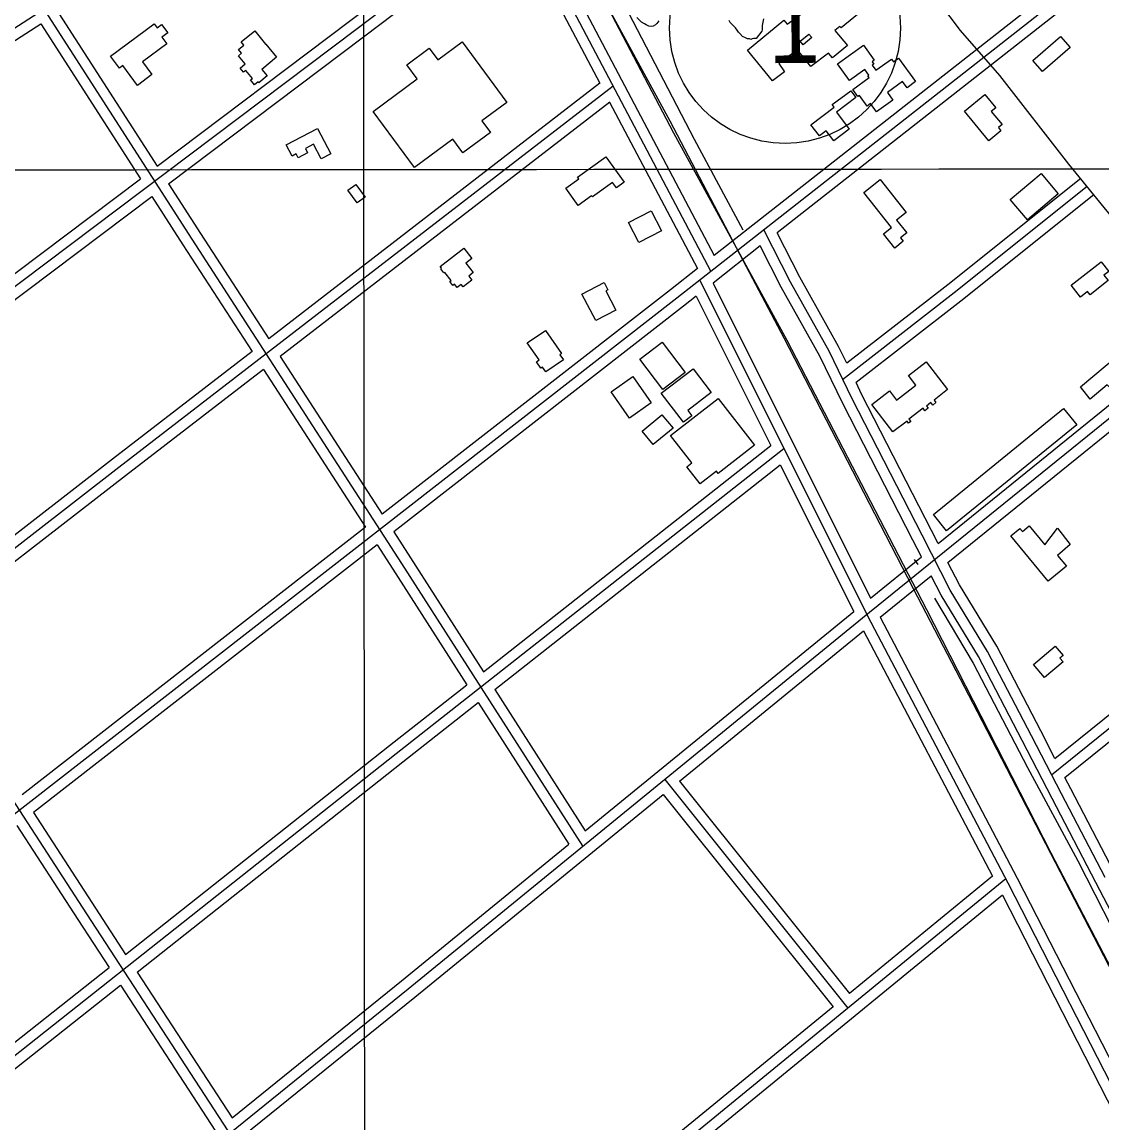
# Model space of a CAD drawing. Extents: x 3297772 to 3335630, y 634068 to 659439.
# Drawn here: x 3311908 to 3313452, y 647184 to 648757 of the extents above; entities that cross this region are included whole.
import ezdxf

# ---------------------------------------------------------------- set-up
doc = ezdxf.new("R2010")
doc.units = 0
for name, color, linetype in [('V-BLDG-OTLN', 7, 'Continuous'), ('V-GRID-MAJR', 7, 'Continuous'), ('V-RAIL-TRAK', 7, 'Continuous'), ('V-ROAD-CNTR', 7, 'Continuous'), ('V-ROAD-IDEN', 7, 'Continuous'), ('V-SITE-VEGE', 7, 'Continuous'), ('V-TOPO-SHOR', 7, 'Continuous')]:
    doc.layers.add(name, color=color, linetype=linetype)

msp = doc.modelspace()

# ---------------------------------------------------------------- linework, layer by layer
at = {"layer": 'V-BLDG-OTLN'}
for points in [[(3313109.589, 648773.9890000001), (3313078.918, 648748.635), (3313077.075, 648750.861), (3313069.884, 648744.902), (3313087.804, 648723.281), (3313066.599, 648705.703), (3313060.929, 648712.5430000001), (3313035.2630000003, 648693.395), (3313016.569, 648717.3250000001), (3312989.748, 648697.615), (3312997.883, 648685.653), (3312980.67, 648673.103), (3312944.932, 648716.899), (3312996.683, 648759.797), (3313001.578, 648753.89), (3313049.204, 648788.317), (3313047.8850000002, 648790.65), (3313079.5470000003, 648814.89)], [(3312034.455, 648708.253), (3312096.5870000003, 648754.341), (3312100.869, 648748.566), (3312107.47, 648753.46), (3312116.11, 648741.809), (3312107.7770000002, 648735.626), (3312115.045, 648725.829), (3312080.168, 648699.958), (3312093.578, 648681.881), (3312072.7970000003, 648666.4670000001), (3312051.838, 648694.7220000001), (3312047.099, 648691.205)], [(3312271.8850000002, 648706.702), (3312250.529, 648689.358), (3312258.1720000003, 648679.943), (3312246.1580000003, 648670.189), (3312245.2060000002, 648671.36), (3312240.1410000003, 648667.248), (3312234.399, 648674.319), (3312237.125, 648676.533), (3312227.88, 648687.9180000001), (3312224.5810000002, 648685.2390000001), (3312219.684, 648691.269), (3312226.903, 648697.132), (3312217.3140000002, 648708.941), (3312221.8200000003, 648712.599), (3312217.521, 648717.889), (3312225.035, 648723.99), (3312221.193, 648728.723), (3312240.514, 648744.412), (3312255.86, 648725.517), (3312256.554, 648725.581)], [(3313036.8170000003, 648734.731), (3313024.362, 648724.4500000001), (3313020.094, 648729.6240000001), (3313032.5470000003, 648739.903)], [(3312469.003, 648548.963), (3312409.81, 648629.028), (3312472.87, 648675.649), (3312457.946, 648695.834), (3312489.889, 648719.449), (3312502.134, 648702.885), (3312536.923, 648728.606), (3312600.907, 648642.059), (3312565.071, 648615.566), (3312577.345, 648598.963), (3312538.238, 648570.052), (3312523.849, 648589.512)], [(3313073.606, 648697.044), (3313110.613, 648723.783), (3313126.055, 648702.408), (3313123.0810000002, 648700.259), (3313125.531, 648696.87), (3313123.3370000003, 648695.285), (3313128.517, 648688.115), (3313150.731, 648704.165), (3313153.576, 648700.231), (3313161, 648705.594), (3313185.2770000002, 648671.991), (3313173.055, 648663.16), (3313166.659, 648672.013), (3313144.915, 648656.305), (3313152.882, 648645.279), (3313129.565, 648628.434), (3313120.88, 648640.456), (3313115.9790000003, 648636.915), (3313105.0100000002, 648652.0970000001), (3313102.661, 648650.4010000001), (3313095.276, 648660.62), (3313118.717, 648677.555), (3313117.031, 648679.89), (3313118.361, 648680.853), (3313112.522, 648688.936), (3313090.801, 648673.242)], [(3313352.898, 648702.004), (3313392.424, 648736.21), (3313405.969, 648720.557), (3313366.443, 648686.351)], [(3313068.5100000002, 648587.083), (3313057.551, 648601.609), (3313047.698, 648594.175), (3313035.56, 648610.2660000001), (3313068.86, 648635.389), (3313066.188, 648638.93), (3313092.519, 648658.796), (3313099.72, 648649.252), (3313071.93, 648628.285), (3313090.489, 648603.6630000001)], [(3313290.075, 648587.279), (3313255.241, 648629.485), (3313284.1380000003, 648653.336), (3313299.699, 648634.484), (3313293.401, 648629.2880000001), (3313308.919, 648610.4890000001), (3313303.498, 648606.015), (3313307.2290000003, 648601.437)], [(3312324.697, 648582.2000000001), (3312312.966, 648576.085), (3312316.184, 648569.917), (3312302.849, 648562.968), (3312299.957, 648568.518), (3312293.819, 648565.321), (3312285.3880000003, 648581.5), (3312330.335, 648604.927), (3312349.269, 648568.6), (3312335.521, 648561.434)], [(3312742.475, 648564.471), (3312768.681, 648527.965), (3312757.542, 648519.968), (3312752.057, 648527.605), (3312723.179, 648506.871), (3312721.9760000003, 648508.544), (3312702.707, 648494.71), (3312685.037, 648519.323), (3312703.616, 648532.659), (3312701.761, 648535.2440000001)], [(3313388.977, 648511.487), (3313345.009, 648474.328), (3313320.594, 648503.215), (3313364.571, 648540.366)], [(3312387.065, 648498.29), (3312373.747, 648516.65), (3312385.117, 648524.897), (3312398.433, 648506.537)], [(3313150.895, 648463.404), (3313111.053, 648513.39), (3313134.497, 648531.965), (3313171.858, 648484.816), (3313158.129, 648473.878), (3313172.659, 648455.513), (3313163.718, 648448.398), (3313167.615, 648443.459), (3313155.534, 648433.917), (3313139.383, 648454.282)], [(3312789.5500000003, 648441.912), (3312775.005, 648470.49), (3312807.362, 648486.958), (3312821.906, 648458.38)], [(3312505.775, 648407.303), (3312539.305, 648433.528), (3312550.7120000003, 648418.9400000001), (3312542.1950000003, 648412.28), (3312552.822, 648398.693), (3312546.401, 648393.672), (3312550.782, 648388.068), (3312538.299, 648378.306), (3312535.492, 648381.894), (3312529.95, 648377.558), (3312526.233, 648382.309), (3312523.914, 648380.497), (3312519.626, 648385.982), (3312521.348, 648387.329), (3312512.1750000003, 648399.058), (3312511.077, 648398.198), (3312506.562, 648403.971), (3312507.6920000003, 648404.854)], [(3313407.6240000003, 648380.608), (3313450.409, 648414.2710000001), (3313461.274, 648400.463), (3313454.452, 648395.095), (3313460.487, 648387.4230000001), (3313434.617, 648367.068), (3313431.057, 648371.59), (3313420.951, 648363.6730000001)], [(3312727.9590000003, 648330.081), (3312708.1380000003, 648368.047), (3312740.06, 648384.712), (3312745.5100000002, 648374.275), (3312742.288, 648372.594), (3312756.657, 648345.0650000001)], [(3312630.1520000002, 648298.206), (3312656.1950000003, 648316.167), (3312679.065, 648283.008), (3312676.7090000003, 648281.384), (3312681.678, 648274.181), (3312656.502, 648256.818), (3312651.769, 648263.681), (3312649.44, 648262.0750000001), (3312643.143, 648271.205), (3312646.95, 648273.854)], [(3312823.873, 648231.5480000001), (3312790.89, 648275.105), (3312822.98, 648299.404), (3312855.961, 648255.845)], [(3313420.949, 648235.155), (3313476.642, 648282.187), (3313491.0270000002, 648265.152), (3313466.342, 648244.307), (3313469.3370000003, 648240.764), (3313462.238, 648234.769), (3313459.23, 648238.333), (3313434.701, 648217.617)], [(3313152.716, 648170.841), (3313122.477, 648210.132), (3313147.864, 648229.67), (3313158.043, 648216.446), (3313185.568, 648237.629), (3313174.955, 648251.42), (3313200.399, 648271.003), (3313230.8880000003, 648231.384), (3313211.534, 648216.4890000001), (3313214.307, 648212.887), (3313209.693, 648209.335), (3313206.9760000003, 648212.868), (3313200.619, 648207.976), (3313203.023, 648204.852), (3313198.421, 648201.311), (3313195.806, 648204.711), (3313175.754, 648189.281), (3313178.275, 648186.007), (3313175.215, 648183.653), (3313173.038, 648186.482)], [(3312776.4450000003, 648190.498), (3312749.819, 648228.281), (3312780.826, 648250.134), (3312807.454, 648212.348)], [(3312821.72, 648226.451), (3312867.202, 648261.127), (3312893.134, 648227.1140000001), (3312859.4790000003, 648201.457), (3312865.203, 648193.949), (3312853.3740000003, 648184.931)], [(3312834.838, 648165.9670000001), (3312903.169, 648218.832), (3312954.938, 648151.916), (3312902.932, 648111.681), (3312900.472, 648114.859), (3312877.098, 648096.775), (3312858.271, 648121.112), (3312865.281, 648126.615)], [(3313210.6210000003, 648052.985), (3313396.784, 648204.412), (3313415.788, 648181.05), (3313229.622, 648029.623)], [(3312794.23, 648171.902), (3312822.6380000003, 648195.384), (3312838.497, 648176.1950000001), (3312810.09, 648152.714)], [(3313374.686, 647957.661), (3313321.406, 648022.408), (3313334.267, 648032.99), (3313337.966, 648028.495), (3313347.704, 648036.509), (3313369.785, 648009.676), (3313387.849, 648033.476), (3313406.3910000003, 648009.991), (3313388.1380000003, 647994.2710000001), (3313400.7060000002, 647979.0750000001)], [(3313353.768, 647838.133), (3313384.717, 647864.542), (3313396.031, 647851.286), (3313391.4960000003, 647847.417), (3313396.08, 647842.047), (3313369.6520000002, 647819.517)]]:
    msp.add_lwpolyline(points, close=True, dxfattribs=at)
at = {"layer": 'V-GRID-MAJR'}
for points in [[(3312404.529, 639457.245), (3312401.887, 642484.8470000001), (3312396.597, 648546.191), (3312391.307, 654607.559), (3312388.66, 657641.312)], [(3301875.511, 648538.54), (3307136.054, 648541.983), (3312396.597, 648546.191), (3317657.139, 648551.165), (3322917.681, 648556.903), (3328178.222, 648563.407), (3333438.761, 648570.676), (3333438.762, 648570.676)]]:
    msp.add_spline(points, degree=3, dxfattribs=at)
at = {"layer": 'V-RAIL-TRAK'}
msp.add_lwpolyline([(3311933.4390000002, 650102.275), (3311944.977, 650085.387), (3311998.0700000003, 650001.669), (3312087.346, 649863.1140000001), (3312125.873, 649803.54), (3312227.4250000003, 649650.8200000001), (3312301.5300000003, 649535.848), (3312326.653, 649495.117), (3312406.5700000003, 649366.599), (3312512.7060000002, 649188.58), (3312622.315, 648999.38), (3312657.245, 648936.973), (3312733.6010000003, 648800.831), (3312833.826, 648615.79), (3312933.883, 648424.533), (3312996.8000000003, 648305.501), (3313095.235, 648115.177), (3313181.713, 647946.845), (3313273.165, 647771.25), (3313378.006, 647568.551), (3313502.654, 647328.138)], dxfattribs=at)
at = {"layer": 'V-ROAD-CNTR'}
for points in [[(3309475.105012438, 654365.6082420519), (3309639.8086830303, 654028.2819167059), (3309845.212272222, 653623.0337272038), (3310156.59264946, 653066.2808407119), (3310529.655903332, 652450.629072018), (3310984.2979940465, 651694.862583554), (3311699.487563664, 650488.0039972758), (3311962.5750374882, 650063.0368472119), (3312156.5306495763, 649765.917441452), (3312337.3872878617, 649482.2870087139), (3312484.708993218, 649240.86949155), (3312633.317696, 648977.5540181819), (3312720.01252261, 648826.4743203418), (3312839.2422841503, 648598.645776), (3313001.19196025, 648301.9423694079), (3313200.674561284, 647917.119139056), (3313378.6912052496, 647569.061835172), (3313539.7338831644, 647260.121453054), (3313882.197198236, 646589.3307946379), (3314289.665383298, 645809.51135428)], [(3310445.758071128, 647292.56838816), (3311429.686103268, 648026.5969201), (3312387.1281883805, 648747.63047803), (3313151.293660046, 649327.1443190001), (3313650.767661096, 649696.2965806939), (3313656.3186499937, 649702.6975678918), (3313657.4956476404, 649707.1285590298), (3313654.611653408, 649713.2485467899), (3313412.689137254, 650029.13291502), (3313159.269644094, 650380.9602113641), (3312980.819000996, 650650.2736727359), (3312864.083234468, 650845.3942824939), (3312685.676591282, 651166.863639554), (3312552.8778568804, 651454.028065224), (3312411.314140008, 651779.201414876), (3312404.497153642, 651786.75939976), (3312395.49317165, 651789.9943932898), (3312011.430939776, 651624.287724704), (3311864.8772328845, 651538.0548971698), (3311646.3846698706, 651445.3270826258)], [(3311222.746517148, 651282.2244088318), (3311498.043966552, 650774.5294242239), (3311655.0506525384, 650506.7089598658), (3311935.203092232, 650064.924843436), (3312111.295740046, 649780.072413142), (3312290.08338247, 649492.4989882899), (3312395.802171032, 649320.8583315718), (3312535.558891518, 649086.606800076), (3312617.9827266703, 648921.211130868), (3312892.461177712, 648400.4261724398)], [(3311339.6702833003, 649727.011519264), (3311683.502595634, 649172.5126282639), (3312150.5706614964, 648446.454080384), (3312450.532061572, 647982.61200807), (3312709.5515435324, 647578.2818167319)], [(3313231.3294999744, 647984.333004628), (3313642.331677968, 648316.99133931), (3314300.2153621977, 648858.0182572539), (3314308.4653456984, 648867.3102386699), (3314315.878330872, 648885.1432030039), (3314314.701333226, 648900.357172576), (3314307.093348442, 648914.8931435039), (3314042.543877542, 649267.3344386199), (3314030.191902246, 649276.2464207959), (3314014.2079342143, 649284.852403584), (3313999.0419645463, 649281.437410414), (3313983.055996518, 649275.043423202), (3313931.1401003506, 649234.315504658)], [(3311916.532129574, 646572.908827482), (3310815.6463313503, 645684.799603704), (3310810.46634171, 645685.5856021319), (3310806.1543503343, 645687.143599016), (3310631.085700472, 645882.5712081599), (3310630.612701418, 645887.728197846), (3310631.81669901, 645897.5761781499), (3311582.242798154, 646664.2096448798), (3312459.8920428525, 647374.3182246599), (3313109.4397437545, 647904.976163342), (3313632.849696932, 648328.6143160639), (3314289.77938307, 648868.8572355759), (3314295.57937147, 648875.389222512), (3314300.6453613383, 648887.5761981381), (3314299.9833626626, 648896.13018103), (3314294.367373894, 648906.8611595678), (3314031.9168987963, 649256.505460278), (3314022.2139182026, 649263.506446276), (3314012.0339385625, 649268.987435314), (3314003.5029556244, 649267.0664391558), (3313990.6229813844, 649261.91444946), (3312843.9892746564, 648362.4012484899), (3311728.172506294, 647492.684987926), (3310776.372409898, 646752.8044676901)], [(3314597.2087682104, 647462.302048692), (3314542.99887663, 647506.06296117), (3314438.248086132, 647598.1047770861), (3314271.87941887, 647738.641496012), (3314144.003674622, 647848.1432770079), (3313900.3651619, 648052.5078682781), (3313827.584307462, 648112.0087492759), (3313784.128394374, 648152.524668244), (3313738.093486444, 648189.4665943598), (3313704.7805530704, 648219.7155338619), (3313669.0786244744, 648249.667473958), (3313630.779701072, 648290.6573919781), (3313574.439813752, 648346.682279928), (3313454.9770526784, 648491.7399898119), (3313404.4491537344, 648553.6678659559), (3313305.8533509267, 648680.7186118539), (3313249.612463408, 648745.0604831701), (3313002.704957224, 649071.6878299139), (3312956.8940488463, 649137.355698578)], [(3313754.219454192, 649095.525782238), (3312897.348167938, 648423.325126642)], [(3310992.331977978, 649049.507874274), (3311234.6884932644, 648679.832613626), (3311615.7517311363, 648074.3818245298), (3312000.2299621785, 647481.84300961), (3312316.86332891, 646995.2549827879), (3312636.259690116, 646495.491982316)], [(3312636.6236893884, 648918.0131372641), (3312897.348167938, 648423.3261266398)], [(3312117.4067278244, 648525.7299218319), (3312396.172170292, 648735.6635019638), (3312612.395737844, 648899.639174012)], [(3312612.395737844, 648899.6401740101), (3312733.700495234, 648669.4806343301)], [(3312101.131760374, 648551.0288712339), (3312378.084206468, 648759.5974540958), (3312516.6809292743, 648864.704243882)], [(3313486.327989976, 648847.24027881), (3312987.3109880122, 648455.769061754)], [(3311925.0951124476, 648824.682323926), (3312101.132760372, 648551.03087123)], [(3310214.2215342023, 647667.0056392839), (3311349.299264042, 648395.2291828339), (3311939.060084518, 648775.247422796)], [(3311415.799131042, 648420.234132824), (3311934.566093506, 648754.5074642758)], [(3311934.566093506, 648754.508464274), (3312077.102808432, 648532.933907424)], [(3313384.465193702, 647703.9975653), (3313555.617851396, 647841.984289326), (3313695.843570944, 647952.506068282), (3313830.262302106, 648068.90683548), (3313892.566177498, 648120.025733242), (3314126.3487099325, 648304.9913633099), (3314207.536547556, 648371.854229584), (3314294.9593727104, 648449.7300738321), (3314575.747811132, 648676.86061957)], [(3312752.8514569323, 648665.316642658), (3312046.505869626, 648119.8877335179), (3311740.230482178, 647882.5402082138)], [(3312733.701495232, 648669.4806343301), (3312260.5024416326, 648304.084365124)], [(3313379.4662037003, 647680.6996118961), (3313564.967832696, 647830.255312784), (3313705.4005518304, 647940.940091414), (3313839.9312827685, 648057.4368584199), (3313901.978158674, 648108.3447566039), (3314135.770691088, 648293.319386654), (3314217.2965280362, 648360.4602523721), (3314304.6703532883, 648438.2920967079), (3314585.181792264, 648665.198642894)], [(3312747.899466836, 648642.5416882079), (3312276.850408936, 648278.8054156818)], [(3312747.898466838, 648642.542688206), (3312873.3562159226, 648404.504164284)], [(3313398.5011656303, 647676.7786197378), (3313574.317813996, 647818.526336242), (3313714.957532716, 647929.3741145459), (3313849.6002634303, 648045.9668813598), (3313911.3901398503, 648096.6637799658), (3314145.1926722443, 648281.647409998), (3314227.0565085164, 648349.0662751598), (3314314.381333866, 648426.8541195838), (3314594.615773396, 648653.5366662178)], [(3311580.32980198, 648158.822655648), (3312077.102808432, 648532.9329074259)], [(3313421.194120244, 648533.3779065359), (3313231.1425003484, 648381.385210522), (3313086.7417891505, 648269.1224350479)], [(3312117.4067278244, 648525.731921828), (3312163.175636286, 648454.5840641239), (3312260.5024416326, 648304.084365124)], [(3313430.5631015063, 648521.662929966), (3313240.430481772, 648369.6062340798), (3313080.677801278, 648245.407482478)], [(3311596.366769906, 648133.3427066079), (3312093.377775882, 648507.6339580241)], [(3312093.377775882, 648507.63595802), (3312137.9656867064, 648438.324096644), (3312236.6744892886, 648285.685401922)], [(3313439.932082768, 648509.9479533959), (3313249.718463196, 648357.827257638), (3313100.0517625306, 648241.4694903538)], [(3313456.067050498, 647533.581906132), (3313393.6331753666, 647653.4906663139), (3313350.9062608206, 647736.3495005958), (3313288.080386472, 647857.00725928), (3313234.805493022, 647944.8350836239), (3313194.4295737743, 648023.20192689), (3313094.5767734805, 648218.257536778), (3313061.8238389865, 648286.308400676), (3313006.33194997, 648385.0562031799), (3312968.364025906, 648459.97105335)], [(3313086.7417891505, 648269.1224350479), (3313075.133812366, 648293.2423868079), (3313019.565923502, 648392.124189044), (3312987.3109880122, 648455.7680617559)], [(3313217.29652804, 648011.5709501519), (3313623.367715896, 648340.2372928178), (3313780.0984024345, 648469.129035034)], [(3312963.2460361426, 648436.89109951), (3312895.614171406, 648383.835205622)], [(3313193.479575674, 647992.2939887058), (3313181.08660046, 648016.3489405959), (3313081.140800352, 648211.5865501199), (3313048.5138656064, 648279.3744145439), (3312993.0979764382, 648377.9882173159), (3312963.2450361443, 648436.8900995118)], [(3312873.35721592, 648404.504164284), (3312834.7492931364, 648374.2172248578), (3312422.7971170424, 648053.1238670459)], [(3312876.726209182, 648388.0821971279), (3313116.5697294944, 647907.7531577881), (3313317.253328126, 647526.101921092), (3313493.7029752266, 647181.039611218), (3313769.917422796, 646659.3126546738), (3313932.621097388, 646342.8922875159)], [(3312895.6131714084, 648383.8342056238), (3313120.582721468, 647933.29210671)], [(3312871.5202195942, 648364.934243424), (3312853.229256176, 648350.5852721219), (3312439.1510843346, 648027.834917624)], [(3312871.519219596, 648364.9332434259), (3312978.15200633, 648151.3826705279)], [(3312236.675489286, 648285.685401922), (3312037.3278879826, 648131.75170979), (3311743.9354747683, 647904.3881645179)], [(3312276.8494089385, 648278.80641568), (3312422.796117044, 648053.1238670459)], [(3312253.0234565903, 648260.4064524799), (3312055.68385127, 648108.023757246), (3311760.323441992, 647879.1342150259)], [(3312253.022456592, 648260.4064524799), (3312399.042164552, 648034.609904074)], [(3313217.29652804, 648011.5709501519), (3313207.772547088, 648030.0549131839), (3313108.012746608, 648224.9285234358), (3313100.0517625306, 648241.4694903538)], [(3315282.628397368, 648233.6475059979), (3315011.0839404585, 648001.5749701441), (3314916.7361291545, 647928.0491171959), (3314763.5024356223, 647798.5713761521), (3314531.7328991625, 647614.9497433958), (3314424.0041146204, 647521.0209312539), (3314229.168504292, 647359.9992532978), (3313935.8680908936, 647123.256726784), (3313859.657243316, 647063.0358472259), (3313768.89042485, 646990.4069924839), (3313762.696437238, 646987.165998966), (3313756.767449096, 646986.941999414), (3313759.866442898, 646985.4220024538), (3313753.001456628, 646998.539976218), (3313629.5927034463, 647234.35350459), (3313582.0577985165, 647325.1853229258), (3313469.364023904, 647540.5228922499), (3313406.9511487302, 647660.3916525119), (3313398.5011656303, 647676.7786197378)], [(3310932.7600971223, 646509.093955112), (3311764.5494335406, 647174.132625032), (3312442.7080772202, 647710.8625515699), (3312997.030968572, 648147.1516789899)], [(3312567.354827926, 647828.0563171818), (3312978.15200633, 648151.380670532)], [(3312583.6137954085, 647802.6763679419), (3312991.8369789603, 648123.974725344)], [(3312991.8369789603, 648123.9767253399), (3313096.710769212, 647913.9471453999)], [(3312399.044164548, 648034.609904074), (3311907.8591469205, 647651.7586697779)], [(3312439.1500843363, 648027.834917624), (3312463.145036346, 647990.7299918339), (3312567.355827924, 647828.05731718)], [(3312415.39813184, 648009.319954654), (3311924.2501141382, 647626.4977203)], [(3312415.3961318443, 648009.3209546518), (3312437.9190867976, 647974.4940243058), (3312543.6698752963, 647809.4153544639)], [(3313120.582721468, 647933.29210671), (3313193.479575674, 647992.2939887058)], [(3313384.465193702, 647703.9975653), (3313364.2242341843, 647743.250486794), (3313301.1593603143, 647864.3682445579), (3313247.9004668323, 647952.1690689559), (3313231.3294999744, 647984.333004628)], [(3313134.4716936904, 647905.938161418), (3313207.513547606, 647965.0580431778)], [(3313902.497157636, 647058.651855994), (3313878.3292059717, 647039.5538941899), (3313785.3683918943, 646965.171042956), (3313770.6024214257, 646957.4440584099), (3313750.34546194, 646956.678059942), (3313737.8384869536, 646962.812047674), (3313726.421509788, 646984.6300040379), (3313603.012756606, 647220.44353241), (3313555.4778516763, 647311.2753507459), (3313442.770077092, 647526.6409200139), (3313380.315202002, 647646.5896801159), (3313337.588287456, 647729.4485143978), (3313275.00141263, 647849.6462740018), (3313221.710519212, 647937.5010982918), (3313207.513547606, 647965.0580431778)], [(3312713.099536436, 647600.5497721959), (3313096.710769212, 647913.9471453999)], [(3313134.4716936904, 647905.938161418), (3313330.5693014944, 647533.0069072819), (3313507.009948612, 647187.96359737), (3313783.216396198, 646666.251640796), (3313936.567089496, 646368.0192372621)], [(3312847.5192675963, 647671.6266300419), (3313110.717741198, 647886.6511999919)], [(3313110.717741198, 647886.6511999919), (3313295.2193721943, 647535.7759017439)], [(3312055.8748508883, 647423.8321256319), (3312433.415095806, 647722.6365280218), (3312543.6698752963, 647809.4153544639)], [(3312583.6147954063, 647802.67736794), (3312713.099536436, 647600.5507721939)], [(3312072.3068180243, 647398.5781761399), (3312452.001058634, 647699.0885751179), (3312559.9288427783, 647784.034405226)], [(3312559.9288427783, 647784.0354052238), (3312689.71258321, 647581.4438104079)], [(3312826.529309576, 647673.848625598), (3313088.282786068, 647346.8322796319)], [(3312847.5192675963, 647671.628630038), (3313090.5107816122, 647368.0522371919)], [(3312224.554513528, 647164.611644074), (3312469.3550239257, 647362.679247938), (3312824.2863140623, 647652.645668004)], [(3312824.2863140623, 647652.647668), (3313067.304828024, 647349.0372752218)], [(3311924.24911414, 647626.4987202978), (3312012.8079370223, 647490.0159932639), (3312055.8748508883, 647423.8321256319)], [(3311900.4981616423, 647607.9867573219), (3311987.6519873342, 647473.6700259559), (3312032.249898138, 647405.134163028)], [(3312208.1045464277, 647189.891593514), (3312450.4290617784, 647385.9572013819), (3312689.71258321, 647581.44281041)], [(3313314.1903342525, 647531.9279094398), (3312008.42394579, 646462.0550491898)], [(3313295.2193721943, 647535.7759017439), (3313090.51178161, 647368.050237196)], [(3313309.3653439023, 647508.58295613), (3312454.3300539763, 646808.0133572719)], [(3313309.3653439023, 647508.58295613), (3313480.39600184, 647174.1156250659), (3313738.612485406, 646686.3846005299)], [(3311506.4419497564, 646986.9739993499), (3311755.2114522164, 647185.871601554), (3312032.249898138, 647405.134163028)], [(3312072.3078180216, 647398.5791761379), (3312208.1045464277, 647189.8925935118)], [(3311522.708917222, 646961.5700501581), (3311773.8874148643, 647162.39364851), (3312048.681865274, 647379.8802135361)], [(3312048.6828652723, 647379.8812135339), (3312184.657593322, 647170.920631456)], [(3313067.3058280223, 647349.036275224), (3312438.0620865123, 646833.4683063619)]]:
    msp.add_lwpolyline(points, dxfattribs=at)
at = {"layer": 'V-ROAD-IDEN'}
msp.add_circle((3312998.5514561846, 648748.3470090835), 165.00000000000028, dxfattribs=at)
msp.add_circle((3312998.5514561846, 648748.3470090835), 165.00000000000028, dxfattribs=at)
at = {"layer": 'V-SITE-VEGE'}
for points in [[(3312818.0640000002, 648758.849), (3312815.451, 648754.968), (3312813.4930000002, 648753.03), (3312810.241, 648751.101), (3312806.995, 648750.466), (3312803.753, 648751.132), (3312799.87, 648753.096), (3312797.929, 648754.402), (3312793.4, 648757.02), (3312786.943, 648763.539)], [(3312967.9560000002, 648761.382), (3312965.965, 648752.307), (3312965.934, 648745.819), (3312965.2770000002, 648743.878), (3312957.441, 648733.531), (3312954.197, 648733.5480000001), (3312951.598, 648732.911), (3312949.65, 648732.272), (3312947.707, 648732.929), (3312945.108, 648732.941), (3312941.872, 648734.254), (3312937.989, 648736.22), (3312934.1180000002, 648740.779), (3312932.181, 648742.737), (3312930.248, 648745.34), (3312927.667, 648748.596), (3312919.918, 648756.42), (3312918.634, 648759.0210000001)]]:
    msp.add_lwpolyline(points, dxfattribs=at)
at = {"layer": 'V-TOPO-SHOR'}
msp.add_line((3313183.358, 647988.627), (3313188.3140000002, 647981.403), dxfattribs=at)
for points in [[(3312688.289, 648926.821), (3312774.68, 648770.08), (3312868.648, 648589.385), (3312938.083, 648460.062)], [(3313212.3680000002, 647933.386), (3313267.453, 647840.009), (3313345.338, 647690.9990000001), (3313417.3170000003, 647557.3910000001), (3313490.105, 647414.384), (3313534.965, 647326.182)]]:
    msp.add_lwpolyline(points, dxfattribs=at)

# ---------------------------------------------------------------- texts
at = {"layer": 'V-ROAD-IDEN'}
msp.add_text('1', height=100.000002, rotation=0.512002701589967, dxfattribs=at).set_placement((3312974.589838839, 648698.130882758))

doc.saveas('drawing.dxf')
